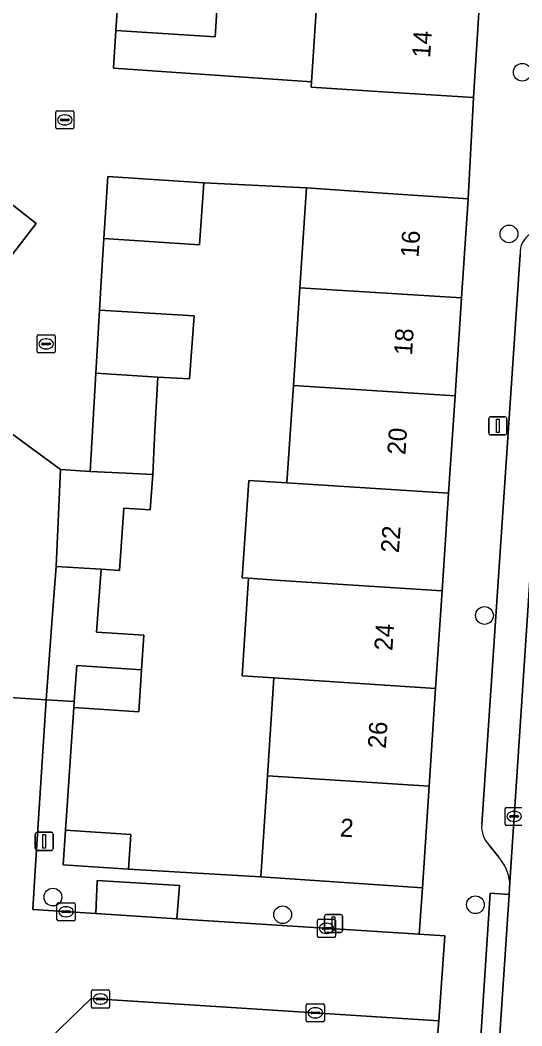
# Model space of a CAD drawing. Extents: x 160349 to 161355, y 381727 to 382854.
# Drawn here: x 160533.4 to 160561.1, y 382138.5 to 382194 of the extents above; entities that cross this region are included whole.
import ezdxf

# ---------------------------------------------------------------- set-up
doc = ezdxf.new("R2010")
doc.units = 0
for name, color, linetype in [('IMGEO_Boom', 7, 'Continuous'), ('IMGEO_Erf', 7, 'Continuous'), ('IMGEO_Kolk', 7, 'Continuous'), ('IMGEO_Lichtmast', 7, 'Continuous'), ('IMGEO_Pand', 7, 'Continuous'), ('IMGEO_Pand_nummerreeks', 7, 'Continuous'), ('IMGEO_Parkeervlak_open', 7, 'Continuous'), ('IMGEO_Rijbaan_lokaal_open', 7, 'Continuous'), ('IMGEO_Voetpad_open', 7, 'Continuous')]:
    doc.layers.add(name, color=color, linetype=linetype)

msp = doc.modelspace()

# ---------------------------------------------------------------- linework, layer by layer
at = {"layer": 'IMGEO_Boom'}
for centre in [(160561.14, 382191.148), (160560.409, 382182.225), (160559.057, 382161.169), (160535.251, 382145.626), (160558.558, 382145.208), (160547.925, 382144.655)]:
    msp.add_circle(centre, 0.489, dxfattribs=at)
at = {"layer": 'IMGEO_Erf'}
msp.add_lwpolyline([(160544.396, 382196.3), (160544.193, 382193.099), (160538.73, 382193.446), (160538.598, 382191.372), (160549.523, 382190.617), (160549.861, 382195.931)], dxfattribs=at)
msp.add_lwpolyline([(160546.054, 382168.62), (160548.158, 382168.485), (160548.516, 382173.864), (160548.875, 382179.253), (160549.242, 382184.764), (160543.567, 382185.043), (160543.339, 382181.626), (160538.062, 382181.978), (160537.932, 382179.922), (160537.822, 382178.018), (160543.047, 382177.709), (160542.786, 382174.221), (160541.034, 382174.328), (160540.882, 382171.378), (160540.757, 382168.95), (160540.624, 382166.999), (160539.154, 382167.099), (160538.919, 382163.66), (160537.919, 382163.722), (160537.656, 382160.251), (160540.27, 382160.077), (160540.143, 382158.172), (160539.989, 382155.854), (160536.408, 382156.092), (160535.947, 382149.323), (160539.555, 382149.083), (160539.427, 382147.159), (160546.711, 382146.74), (160547.043, 382151.729), (160547.082, 382152.317), (160547.442, 382157.727), (160545.688, 382157.843), (160546.046, 382163.22), (160545.696, 382163.243)], close=True, dxfattribs=at)
at = {"layer": 'IMGEO_Kolk'}
for p, q in [((160535.48, 382189.019), (160536.332, 382189.019)), ((160535.405, 382188.093), (160535.405, 382188.945)), ((160535.664, 382188.513), (160535.664, 382188.525)), ((160536.102, 382188.476), (160535.704, 382188.476)), ((160535.707, 382188.562), (160536.105, 382188.562)), ((160535.893, 382188.799), (160535.918, 382188.799)), ((160536.148, 382188.525), (160536.148, 382188.513)), ((160536.406, 382188.945), (160536.406, 382188.093)), ((160536.332, 382188.019), (160535.48, 382188.019)), ((160535.916, 382188.239), (160535.891, 382188.239)), ((160534.377, 382175.73), (160534.377, 382176.582)), ((160534.452, 382176.656), (160535.304, 382176.656)), ((160534.865, 382176.436), (160534.89, 382176.436)), ((160535.378, 382176.582), (160535.378, 382175.73)), ((160534.636, 382176.15), (160534.636, 382176.162)), ((160535.074, 382176.113), (160534.676, 382176.113)), ((160534.679, 382176.199), (160535.077, 382176.199)), ((160534.888, 382175.876), (160534.863, 382175.876)), ((160535.12, 382176.162), (160535.12, 382176.15)), ((160535.304, 382175.656), (160534.452, 382175.656)), ((160560.192, 382149.653), (160560.192, 382150.505)), ((160560.267, 382150.579), (160561.119, 382150.579)), ((160560.68, 382150.359), (160560.705, 382150.359)), ((160560.451, 382150.073), (160560.451, 382150.085)), ((160560.889, 382150.036), (160560.491, 382150.036)), ((160560.494, 382150.122), (160560.892, 382150.122)), ((160560.703, 382149.799), (160560.678, 382149.799)), ((160560.935, 382150.085), (160560.935, 382150.073)), ((160561.119, 382149.579), (160560.267, 382149.579)), ((160535.474, 382144.392), (160535.474, 382145.244)), ((160535.549, 382145.318), (160536.401, 382145.318)), ((160536.475, 382145.244), (160536.475, 382144.392)), ((160535.733, 382144.812), (160535.733, 382144.824)), ((160536.171, 382144.775), (160535.773, 382144.775)), ((160535.776, 382144.861), (160536.174, 382144.861)), ((160535.962, 382145.098), (160535.987, 382145.098)), ((160536.217, 382144.824), (160536.217, 382144.812)), ((160536.401, 382144.318), (160535.549, 382144.318)), ((160535.985, 382144.538), (160535.96, 382144.538)), ((160549.844, 382143.475), (160549.844, 382144.327)), ((160549.919, 382144.401), (160550.771, 382144.401)), ((160550.332, 382144.181), (160550.357, 382144.181)), ((160550.845, 382144.327), (160550.845, 382143.475)), ((160550.103, 382143.895), (160550.103, 382143.907)), ((160550.541, 382143.858), (160550.143, 382143.858)), ((160550.146, 382143.944), (160550.544, 382143.944)), ((160550.355, 382143.621), (160550.33, 382143.621)), ((160550.587, 382143.907), (160550.587, 382143.895)), ((160550.771, 382143.401), (160549.919, 382143.401)), ((160537.371, 382139.576), (160537.371, 382140.428)), ((160537.446, 382140.502), (160538.298, 382140.502)), ((160537.859, 382140.282), (160537.884, 382140.282)), ((160538.372, 382140.428), (160538.372, 382139.576)), ((160537.63, 382139.996), (160537.63, 382140.008)), ((160538.068, 382139.959), (160537.67, 382139.959)), ((160537.673, 382140.045), (160538.071, 382140.045)), ((160537.882, 382139.722), (160537.857, 382139.722)), ((160538.114, 382140.008), (160538.114, 382139.996)), ((160549.225, 382138.814), (160549.225, 382139.666)), ((160549.3, 382139.74), (160550.152, 382139.74)), ((160550.226, 382139.666), (160550.226, 382138.814)), ((160538.298, 382139.502), (160537.446, 382139.502)), ((160549.484, 382139.234), (160549.484, 382139.246)), ((160549.922, 382139.197), (160549.524, 382139.197)), ((160549.527, 382139.283), (160549.925, 382139.283)), ((160549.713, 382139.52), (160549.738, 382139.52)), ((160549.968, 382139.246), (160549.968, 382139.234)), ((160550.152, 382138.74), (160549.3, 382138.74)), ((160549.736, 382138.96), (160549.711, 382138.96))]:
    msp.add_line(p, q, dxfattribs=at)
for points in [[(160535.48, 382189.019), (160536.332, 382189.019)], [(160535.405, 382188.093), (160535.405, 382188.945)], [(160536.406, 382188.945), (160536.406, 382188.093)], [(160536.332, 382188.019), (160535.48, 382188.019)], [(160534.377, 382175.73), (160534.377, 382176.582)], [(160534.452, 382176.656), (160535.304, 382176.656)], [(160535.378, 382176.582), (160535.378, 382175.73)], [(160535.304, 382175.656), (160534.452, 382175.656)], [(160560.192, 382149.653), (160560.192, 382150.505)], [(160560.267, 382150.579), (160561.119, 382150.579)], [(160561.119, 382149.579), (160560.267, 382149.579)], [(160535.474, 382144.392), (160535.474, 382145.244)], [(160535.549, 382145.318), (160536.401, 382145.318)], [(160536.475, 382145.244), (160536.475, 382144.392)], [(160536.401, 382144.318), (160535.549, 382144.318)], [(160549.844, 382143.475), (160549.844, 382144.327)], [(160549.919, 382144.401), (160550.771, 382144.401)], [(160550.845, 382144.327), (160550.845, 382143.475)], [(160550.771, 382143.401), (160549.919, 382143.401)], [(160537.371, 382139.576), (160537.371, 382140.428)], [(160537.446, 382140.502), (160538.298, 382140.502)], [(160538.372, 382140.428), (160538.372, 382139.576)], [(160549.225, 382138.814), (160549.225, 382139.666)], [(160549.3, 382139.74), (160550.152, 382139.74)], [(160550.226, 382139.666), (160550.226, 382138.814)], [(160538.298, 382139.502), (160537.446, 382139.502)], [(160550.152, 382138.74), (160549.3, 382138.74)]]:
    msp.add_lwpolyline(points, dxfattribs=at)
for centre, radius, start, end in [((160535.482, 382188.943), 0.0765, 91.552, 178.448), ((160535.482, 382188.943), 0.0765, 91.552, 178.448), ((160536.33, 382188.943), 0.0765, 1.552, 88.448), ((160536.33, 382188.943), 0.0765, 1.552, 88.448), ((160535.704, 382188.522), 0.0403, 85.8775, 175.7526), ((160535.701, 382188.512), 0.0366, 178.938, 274.7102), ((160536.105, 382188.519), 0.043, 264.8664, 352.4533), ((160536.109, 382188.524), 0.0386, 1.7309, 96.639), ((160535.482, 382188.095), 0.0765, 181.552, 268.448), ((160535.482, 382188.095), 0.0765, 181.552, 268.448), ((160536.33, 382188.095), 0.0765, 271.552, 358.448), ((160536.33, 382188.095), 0.0765, 271.552, 358.448), ((160534.454, 382176.58), 0.0765, 91.552, 178.448), ((160534.454, 382176.58), 0.0765, 91.552, 178.448), ((160535.302, 382176.58), 0.0765, 1.552, 88.448), ((160535.302, 382176.58), 0.0765, 1.552, 88.448), ((160534.454, 382175.732), 0.0765, 181.552, 268.448), ((160534.454, 382175.732), 0.0765, 181.552, 268.448), ((160534.676, 382176.159), 0.0403, 85.8775, 175.7526), ((160534.673, 382176.149), 0.0366, 178.938, 274.7102), ((160535.077, 382176.156), 0.043, 264.8664, 352.4533), ((160535.081, 382176.161), 0.0386, 1.7309, 96.639), ((160535.302, 382175.732), 0.0765, 271.552, 358.448), ((160535.302, 382175.732), 0.0765, 271.552, 358.448), ((160560.269, 382150.503), 0.0765, 91.552, 178.448), ((160560.269, 382150.503), 0.0765, 91.552, 178.448), ((160560.269, 382149.655), 0.0765, 181.552, 268.448), ((160560.269, 382149.655), 0.0765, 181.552, 268.448), ((160560.491, 382150.082), 0.0403, 85.8775, 175.7526), ((160560.488, 382150.072), 0.0366, 178.938, 274.7102), ((160560.892, 382150.079), 0.043, 264.8664, 352.4533), ((160560.896, 382150.084), 0.0386, 1.7309, 96.639), ((160535.551, 382145.242), 0.0765, 91.552, 178.448), ((160535.551, 382145.242), 0.0765, 91.552, 178.448), ((160536.399, 382145.242), 0.0765, 1.552, 88.448), ((160536.399, 382145.242), 0.0765, 1.552, 88.448), ((160535.773, 382144.821), 0.0403, 85.8775, 175.7526), ((160535.77, 382144.811), 0.0366, 178.938, 274.7102), ((160536.174, 382144.818), 0.043, 264.8664, 352.4533), ((160536.178, 382144.823), 0.0386, 1.7309, 96.639), ((160535.551, 382144.394), 0.0765, 181.552, 268.448), ((160535.551, 382144.394), 0.0765, 181.552, 268.448), ((160536.399, 382144.394), 0.0765, 271.552, 358.448), ((160536.399, 382144.394), 0.0765, 271.552, 358.448), ((160549.921, 382144.325), 0.0765, 91.552, 178.448), ((160549.921, 382144.325), 0.0765, 91.552, 178.448), ((160550.769, 382144.325), 0.0765, 1.552, 88.448), ((160550.769, 382144.325), 0.0765, 1.552, 88.448), ((160550.143, 382143.904), 0.0403, 85.8775, 175.7526), ((160550.14, 382143.894), 0.0366, 178.938, 274.7102), ((160550.544, 382143.901), 0.043, 264.8664, 352.4533), ((160550.548, 382143.906), 0.0386, 1.7309, 96.639), ((160549.921, 382143.477), 0.0765, 181.552, 268.448), ((160549.921, 382143.477), 0.0765, 181.552, 268.448), ((160550.769, 382143.477), 0.0765, 271.552, 358.448), ((160550.769, 382143.477), 0.0765, 271.552, 358.448), ((160537.448, 382140.426), 0.0765, 91.552, 178.448), ((160537.448, 382140.426), 0.0765, 91.552, 178.448), ((160538.296, 382140.426), 0.0765, 1.552, 88.448), ((160538.296, 382140.426), 0.0765, 1.552, 88.448), ((160537.67, 382140.005), 0.0403, 85.8775, 175.7526), ((160537.667, 382139.995), 0.0366, 178.938, 274.7102), ((160538.071, 382140.002), 0.043, 264.8664, 352.4533), ((160538.075, 382140.007), 0.0386, 1.7309, 96.639), ((160549.302, 382139.664), 0.0765, 91.552, 178.448), ((160549.302, 382139.664), 0.0765, 91.552, 178.448), ((160550.15, 382139.664), 0.0765, 1.552, 88.448), ((160550.15, 382139.664), 0.0765, 1.552, 88.448), ((160537.448, 382139.578), 0.0765, 181.552, 268.448), ((160537.448, 382139.578), 0.0765, 181.552, 268.448), ((160538.296, 382139.578), 0.0765, 271.552, 358.448), ((160538.296, 382139.578), 0.0765, 271.552, 358.448), ((160549.524, 382139.243), 0.0403, 85.8775, 175.7526), ((160549.521, 382139.233), 0.0366, 178.938, 274.7102), ((160549.925, 382139.24), 0.043, 264.8664, 352.4533), ((160549.929, 382139.245), 0.0386, 1.7309, 96.639), ((160549.302, 382138.816), 0.0765, 181.552, 268.448), ((160549.302, 382138.816), 0.0765, 181.552, 268.448), ((160550.15, 382138.816), 0.0765, 271.552, 358.448), ((160550.15, 382138.816), 0.0765, 271.552, 358.448)]:
    msp.add_arc(centre, radius, start, end, dxfattribs=at)
for centre, major_axis, ratio, start_param, end_param in [((160535.892, 382188.519), (-0.387, 0.002), 0.722429, 4.712389, 7.853982), ((160535.917, 382188.519), (-0.39, 0.002), 0.717154, 1.570796, 4.712389), ((160534.864, 382176.156), (-0.387, 0.002), 0.722429, 4.712389, 7.853982), ((160534.889, 382176.156), (-0.39, 0.002), 0.717154, 1.570796, 4.712389), ((160560.679, 382150.079), (-0.387, 0.002), 0.722429, 4.712389, 7.853982), ((160560.704, 382150.079), (-0.39, 0.002), 0.717154, 1.570796, 4.712389), ((160535.961, 382144.818), (-0.387, 0.002), 0.722429, 4.712389, 7.853982), ((160535.986, 382144.818), (-0.39, 0.002), 0.717154, 1.570796, 4.712389), ((160550.331, 382143.901), (-0.387, 0.002), 0.722429, 4.712389, 7.853982), ((160550.356, 382143.901), (-0.39, 0.002), 0.717154, 1.570796, 4.712389), ((160537.858, 382140.002), (-0.387, 0.002), 0.722429, 4.712389, 7.853982), ((160537.883, 382140.002), (-0.39, 0.002), 0.717154, 1.570796, 4.712389), ((160549.712, 382139.24), (-0.387, 0.002), 0.722429, 4.712389, 7.853982), ((160549.737, 382139.24), (-0.39, 0.002), 0.717154, 1.570796, 4.712389)]:
    msp.add_ellipse(centre, major_axis=major_axis, ratio=ratio, start_param=start_param, end_param=end_param, dxfattribs=at)
at = {"layer": 'IMGEO_Lichtmast'}
for p, q in [((160559.291, 382171.236), (160559.291, 382172.036)), ((160559.291, 382172.036), (160559.291, 382171.236)), ((160559.391, 382172.136), (160560.181, 382172.136)), ((160560.181, 382172.136), (160559.391, 382172.136)), ((160560.281, 382172.036), (160560.281, 382171.236)), ((160560.281, 382171.236), (160560.281, 382172.036)), ((160560.181, 382171.136), (160559.391, 382171.136)), ((160559.391, 382171.136), (160560.181, 382171.136)), ((160534.281, 382148.306), (160534.281, 382149.106)), ((160534.281, 382149.106), (160534.281, 382148.306)), ((160534.381, 382149.206), (160535.171, 382149.206)), ((160535.171, 382149.206), (160534.381, 382149.206)), ((160535.271, 382149.106), (160535.271, 382148.306)), ((160535.271, 382148.306), (160535.271, 382149.106)), ((160535.171, 382148.206), (160534.381, 382148.206)), ((160534.381, 382148.206), (160535.171, 382148.206)), ((160550.334, 382144.669), (160551.124, 382144.669)), ((160551.124, 382144.669), (160550.334, 382144.669)), ((160550.234, 382143.769), (160550.234, 382144.569)), ((160550.234, 382144.569), (160550.234, 382143.769)), ((160551.224, 382144.569), (160551.224, 382143.769)), ((160551.224, 382143.769), (160551.224, 382144.569)), ((160551.124, 382143.669), (160550.334, 382143.669)), ((160550.334, 382143.669), (160551.124, 382143.669))]:
    msp.add_line(p, q, dxfattribs=at)
for points in [[(160559.711, 382172.011), (160559.861, 382172.011), (160559.861, 382171.261), (160559.711, 382171.261), (160559.711, 382172.011)], [(160534.701, 382149.081), (160534.851, 382149.081), (160534.851, 382148.331), (160534.701, 382148.331), (160534.701, 382149.081)], [(160550.654, 382144.544), (160550.804, 382144.544), (160550.804, 382143.794), (160550.654, 382143.794), (160550.654, 382144.544)]]:
    msp.add_lwpolyline(points, dxfattribs=at)
for centre, start, end in [((160559.391, 382172.036), 90, 180), ((160559.391, 382172.036), 90, 180), ((160560.181, 382172.036), 0, 90), ((160560.181, 382172.036), 360, 90), ((160559.391, 382171.236), 180, 270), ((160559.391, 382171.236), 180, 270), ((160560.181, 382171.236), 270, 0), ((160560.181, 382171.236), 270, 0), ((160534.381, 382149.106), 90, 180), ((160534.381, 382149.106), 90, 180), ((160535.171, 382149.106), 0, 90), ((160535.171, 382149.106), 360, 90), ((160534.381, 382148.306), 180, 270), ((160534.381, 382148.306), 180, 270), ((160535.171, 382148.306), 270, 0), ((160535.171, 382148.306), 270, 0), ((160550.334, 382144.569), 90, 180), ((160550.334, 382144.569), 90, 180), ((160551.124, 382144.569), 0, 90), ((160551.124, 382144.569), 360, 90), ((160550.334, 382143.769), 180, 270), ((160550.334, 382143.769), 180, 270), ((160551.124, 382143.769), 270, 0), ((160551.124, 382143.769), 270, 0)]:
    msp.add_arc(centre, 0.1, start, end, dxfattribs=at)
at = {"layer": 'IMGEO_Pand'}
for points in [[(160544.396, 382196.3), (160538.935, 382196.669), (160538.73, 382193.446), (160544.193, 382193.099)], [(160558.799, 382195.327), (160549.861, 382195.931), (160549.523, 382190.617), (160549.505, 382190.329), (160553.455, 382190.077), (160558.444, 382189.759)], [(160531.782, 382184.789), (160523.75, 382191.07), (160520.85, 382187.34), (160526.928, 382182.616), (160531.402, 382179.031), (160534.324, 382182.801)], [(160543.567, 382185.043), (160538.279, 382185.395), (160538.062, 382181.978), (160543.339, 382181.626)], [(160557.795, 382178.692), (160558.16, 382184.17), (160553.172, 382184.502), (160549.242, 382184.764), (160548.875, 382179.253)], [(160557.795, 382178.692), (160548.875, 382179.253), (160548.516, 382173.864), (160557.436, 382173.292)], [(160543.047, 382177.709), (160537.822, 382178.018), (160537.621, 382174.536), (160541.034, 382174.328), (160542.786, 382174.221)], [(160535.662, 382169.225), (160529.614, 382173.66), (160528.494, 382174.482), (160525.01, 382169.86), (160525.163, 382169.619), (160529.701, 382166.291), (160529.303, 382159.852), (160529.12, 382156.888), (160534.872, 382156.518), (160535.249, 382161.504), (160535.429, 382163.878)], [(160541.034, 382174.328), (160537.621, 382174.536), (160537.308, 382169.114), (160539.285, 382169.025), (160540.757, 382168.95), (160540.882, 382171.378)], [(160557.078, 382167.913), (160557.436, 382173.292), (160548.516, 382173.864), (160548.158, 382168.485)], [(160539.154, 382167.099), (160540.624, 382166.999), (160540.757, 382168.95), (160539.285, 382169.025), (160537.308, 382169.114), (160535.662, 382169.225), (160535.429, 382163.878), (160537.919, 382163.722), (160538.919, 382163.66)], [(160557.078, 382167.913), (160548.158, 382168.485), (160546.054, 382168.62), (160545.696, 382163.243), (160546.046, 382163.22), (160547.8, 382163.105), (160556.719, 382162.524)], [(160540.27, 382160.077), (160537.656, 382160.251), (160537.919, 382163.722), (160535.429, 382163.878), (160535.249, 382161.504), (160534.872, 382156.518), (160536.43, 382156.421), (160536.562, 382158.408), (160540.143, 382158.172)], [(160556.719, 382162.524), (160547.8, 382163.105), (160546.046, 382163.22), (160545.688, 382157.843), (160547.442, 382157.727), (160556.36, 382157.135)], [(160536.562, 382158.408), (160536.43, 382156.421), (160536.408, 382156.092), (160539.989, 382155.854), (160540.143, 382158.172)], [(160547.082, 382152.317), (160556.002, 382151.755), (160556.36, 382157.135), (160547.442, 382157.727)], [(160547.082, 382152.317), (160547.043, 382151.729), (160546.711, 382146.74), (160555.629, 382146.146), (160556.002, 382151.755)], [(160535.947, 382149.323), (160535.819, 382147.399), (160539.427, 382147.159), (160539.555, 382149.083)]]:
    msp.add_lwpolyline(points, close=True, dxfattribs=at)
at = {"layer": 'IMGEO_Parkeervlak_open'}
for points in [[(160560.456, 382146.449), (160562.945, 382183.938)], [(160561.024, 382181.097), (160558.907, 382149.631)], [(160559.313, 382148.501), (160559.846, 382147.828)]]:
    msp.add_lwpolyline(points, dxfattribs=at)
msp.add_lwpolyline([(160542.093, 382144.429), (160542.234, 382146.268), (160537.701, 382146.536), (160537.614, 382144.715)], close=True, dxfattribs=at)
for centre, radius, start, end in [((160562.207, 382181.202), 1.187, 120.2786, 185.0603), ((160560.293, 382149.491), 1.393, 174.2327, 225.2932), ((160557.875, 382146.132), 2.601, 7.0094, 40.7149)]:
    msp.add_arc(centre, radius, start, end, dxfattribs=at)
at = {"layer": 'IMGEO_Rijbaan_lokaal_open'}
for points in [[(160529.614, 382173.66), (160535.662, 382169.225), (160537.308, 382169.114), (160537.621, 382174.536), (160537.822, 382178.018), (160537.932, 382179.922), (160538.062, 382181.978), (160538.279, 382185.395), (160543.567, 382185.043), (160549.242, 382184.764), (160553.172, 382184.502), (160558.16, 382184.17), (160558.444, 382189.759), (160553.455, 382190.077), (160549.505, 382190.329), (160549.523, 382190.617), (160538.598, 382191.372), (160538.73, 382193.446), (160538.935, 382196.669)], [(160531.782, 382184.789), (160534.324, 382182.801), (160531.402, 382179.031)], [(160563.973, 382127.912), (160565.164, 382144.957), (160565.301, 382146.8), (160565.486, 382149.584), (160566.437, 382164.19), (160567.561, 382181.023), (160567.738, 382183.56), (160562.945, 382183.938), (160560.456, 382146.449), (160560.412, 382145.778), (160559.779, 382136.133), (160559.743, 382135.586), (160559.102, 382125.821), (160558.953, 382123.558)]]:
    msp.add_lwpolyline(points, dxfattribs=at)
msp.add_lwpolyline([(160556.874, 382143.486), (160555.458, 382143.576), (160542.093, 382144.429), (160537.614, 382144.715), (160534.145, 382144.936), (160534.28, 382147.094), (160534.872, 382156.518), (160529.12, 382156.888), (160529.015, 382155.582), (160528.241, 382145.991), (160528.597, 382145.965), (160528.265, 382141), (160530.513, 382140.848), (160530.449, 382140.022), (160530.728, 382140.022), (160529.734, 382125.293), (160534.153, 382124.984), (160535.032, 382137.762), (160537.357, 382140.034), (160556.542, 382138.8)], close=True, dxfattribs=at)
at = {"layer": 'IMGEO_Voetpad_open'}
for points in [[(160564.097, 382228.603), (160563.969, 382228.451), (160560.815, 382224.738), (160559.424, 382222.918), (160560.539, 382221.977), (160560.18, 382216.966), (160559.842, 382211.675), (160559.488, 382206.127), (160559.144, 382200.737), (160558.799, 382195.327), (160558.444, 382189.759), (160558.16, 382184.17), (160557.795, 382178.692), (160557.436, 382173.292), (160557.078, 382167.913), (160556.719, 382162.524), (160556.36, 382157.135), (160556.002, 382151.755), (160555.629, 382146.146), (160555.458, 382143.576), (160556.874, 382143.486), (160556.542, 382138.8), (160556.158, 382134.351)], [(160558.907, 382149.631), (160561.024, 382181.097)], [(160559.846, 382147.828), (160559.313, 382148.501)], [(160559.743, 382135.586), (160559.779, 382136.133), (160558.741, 382136.201), (160559.374, 382145.846), (160560.412, 382145.778), (160560.456, 382146.449)], [(160556.133, 382134.259), (160556.158, 382134.351), (160556.542, 382138.8), (160537.357, 382140.034), (160535.032, 382137.762), (160534.153, 382124.984), (160533.945, 382121.958), (160533.754, 382119.181), (160533.568, 382116.409)]]:
    msp.add_lwpolyline(points, dxfattribs=at)
for points in [[(160555.629, 382146.146), (160546.711, 382146.74), (160539.427, 382147.159), (160535.819, 382147.399), (160535.947, 382149.323), (160536.408, 382156.092), (160536.43, 382156.421), (160534.872, 382156.518), (160534.28, 382147.094), (160534.145, 382144.936), (160537.614, 382144.715), (160537.701, 382146.536), (160542.234, 382146.268), (160542.093, 382144.429), (160555.458, 382143.576)], [(160559.779, 382136.133), (160560.412, 382145.778), (160559.374, 382145.846), (160558.741, 382136.201)]]:
    msp.add_lwpolyline(points, close=True, dxfattribs=at)
for centre, radius, start, end in [((160562.207, 382181.202), 1.187, 120.2786, 185.0603), ((160560.293, 382149.491), 1.393, 174.2327, 225.2932), ((160557.875, 382146.132), 2.601, 7.0094, 40.7149)]:
    msp.add_arc(centre, radius, start, end, dxfattribs=at)

# ---------------------------------------------------------------- texts
at = {"layer": 'IMGEO_Pand_nummerreeks'}
for s, rotation, p in [('14', 86.3505, (160556.057, 382191.925)), ('16', 86.1918, (160555.417, 382180.902)), ('18', 86.1918, (160555.057, 382175.503)), ('20', 86.1918, (160554.691, 382170.01)), ('22', 86.19, (160554.333, 382164.601)), ('24', 86.19, (160553.973, 382159.201)), ('26', 86.1918, (160553.613, 382153.8)), ('2', 356.1893, (160551.061, 382148.976))]:
    msp.add_text(s, height=1, rotation=rotation, dxfattribs=at).set_placement(p)

doc.saveas('drawing.dxf')
